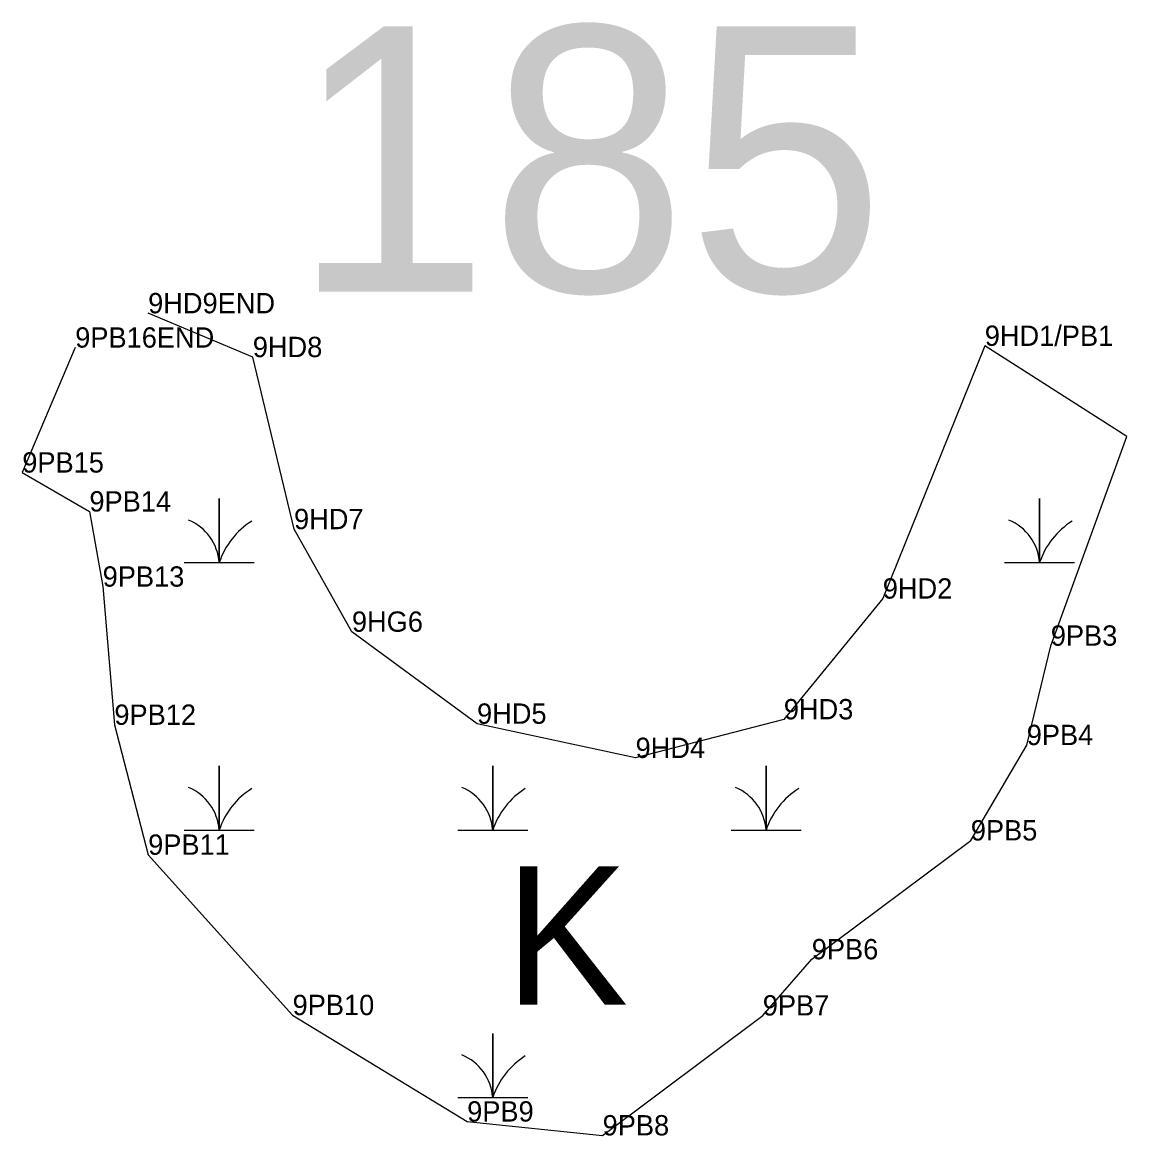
# Model space of a CAD drawing. Extents: x 2072529 to 2268796, y 436423 to 470406.
# Drawn here: x 2214651 to 2214922.6, y 450641.4 to 450915.4 of the extents above; entities that cross this region are included whole.
import ezdxf

# ---------------------------------------------------------------- set-up
doc = ezdxf.new("R2010")
doc.units = 0
for name, color, linetype in [('Default', 7, 'Continuous'), ('Exist Environmental Wetland Boundary', 7, 'Continuous'), ('Exist Environmental Wetland Boundary Cogo Comment', 7, 'Continuous'), ('Exist Hydro Swamp or Marsh', 7, 'Continuous'), ('Old_Level_20', 7, 'Continuous')]:
    doc.layers.add(name, color=color, linetype=linetype)

msp = doc.modelspace()

# ---------------------------------------------------------------- linework, layer by layer
at = {"layer": 'Exist Environmental Wetland Boundary'}
msp.add_lwpolyline([(2214663.98, 450835.35), (2214650.96, 450804.61), (2214667.47, 450795.03), (2214670.73, 450776.54), (2214673.61, 450742.54), (2214681.92, 450710.57), (2214717.44, 450671.12), (2214760.37, 450644.93), (2214793.69, 450641.52), (2214833.07, 450671.03), (2214845.12, 450684.85), (2214884.23, 450714.09), (2214897.98, 450737.56), (2214903.9, 450762.01), (2214922.57, 450813.5), (2214887.66, 450835.78), (2214862.58, 450773.6), (2214838.24, 450743.89), (2214801.78, 450734.39), (2214762.8, 450742.81), (2214732.03, 450765.44), (2214717.79, 450790.68), (2214707.65, 450833.02), (2214681.91, 450843.8)], dxfattribs=at)
at = {"layer": 'Exist Hydro Swamp or Marsh'}
for points in [[(2214690.8, 450782.46), (2214699.4, 450782.46), (2214699.4, 450798.24), (2214699.4, 450782.46), (2214708, 450782.46)], [(2214892.55, 450782.46), (2214901.15, 450782.46), (2214901.15, 450798.24), (2214901.15, 450782.46), (2214909.75, 450782.46)], [(2214690.8, 450716.66), (2214699.4, 450716.66), (2214699.4, 450732.44), (2214699.4, 450716.66), (2214708, 450716.66)], [(2214758.05, 450716.66), (2214766.65, 450716.66), (2214766.65, 450732.44), (2214766.65, 450716.66), (2214775.25, 450716.66)], [(2214825.3, 450716.66), (2214833.9, 450716.66), (2214833.9, 450732.44), (2214833.9, 450716.66), (2214842.5, 450716.66)], [(2214758.05, 450650.86), (2214766.65, 450650.86), (2214766.65, 450666.64), (2214766.65, 450650.86), (2214775.25, 450650.86)]]:
    msp.add_lwpolyline(points, dxfattribs=at)
for centre, radius, start, end in [((2214687.13, 450781.57), 12.3, 4.1403, 67.535), ((2214717.64, 450776.4), 19.22, 122.1274, 161.6222), ((2214888.88, 450781.57), 12.3, 4.1403, 67.535), ((2214919.39, 450776.4), 19.22, 122.1274, 161.6222), ((2214687.13, 450715.77), 12.3, 4.1403, 67.535), ((2214717.64, 450710.6), 19.22, 122.1274, 161.6222), ((2214754.38, 450715.77), 12.3, 4.1403, 67.535), ((2214784.89, 450710.6), 19.22, 122.1274, 161.6222), ((2214821.63, 450715.77), 12.3, 4.1403, 67.535), ((2214852.14, 450710.6), 19.22, 122.1274, 161.6222), ((2214754.38, 450649.97), 12.3, 4.1403, 67.535), ((2214784.89, 450644.8), 19.22, 122.1274, 161.6222)]:
    msp.add_arc(centre, radius, start, end, dxfattribs=at)
at = {"layer": 'Old_Level_20'}
for p, q in [((2214681.91, 450843.8), (2214681.91, 450843.8)), ((2214663.98, 450835.35), (2214663.98, 450835.35)), ((2214887.66, 450835.78), (2214887.66, 450835.78)), ((2214707.65, 450833.02), (2214707.65, 450833.02)), ((2214922.57, 450813.5), (2214922.57, 450813.5)), ((2214650.96, 450804.61), (2214650.96, 450804.61)), ((2214667.47, 450795.03), (2214667.47, 450795.03)), ((2214717.79, 450790.68), (2214717.79, 450790.68)), ((2214670.73, 450776.54), (2214670.73, 450776.54)), ((2214862.58, 450773.6), (2214862.58, 450773.6)), ((2214732.03, 450765.44), (2214732.03, 450765.44)), ((2214903.9, 450762.01), (2214903.9, 450762.01)), ((2214762.8, 450742.81), (2214762.8, 450742.81)), ((2214838.24, 450743.89), (2214838.24, 450743.89)), ((2214673.61, 450742.54), (2214673.61, 450742.54)), ((2214897.98, 450737.56), (2214897.98, 450737.56)), ((2214801.78, 450734.39), (2214801.78, 450734.39)), ((2214884.23, 450714.09), (2214884.23, 450714.09)), ((2214681.92, 450710.57), (2214681.92, 450710.57)), ((2214845.12, 450684.85), (2214845.12, 450684.85)), ((2214717.44, 450671.12), (2214717.44, 450671.12)), ((2214833.07, 450671.03), (2214833.07, 450671.03)), ((2214760.37, 450644.93), (2214760.37, 450644.93)), ((2214793.69, 450641.52), (2214793.69, 450641.52))]:
    msp.add_line(p, q, dxfattribs=at)

# ---------------------------------------------------------------- texts
at = {"layer": 'Default'}
msp.add_text('185', height=65.34, dxfattribs=at).set_placement((2214717.3, 450849.09))
at = {"layer": 'Exist Environmental Wetland Boundary Cogo Comment'}
for s, p in [('9HD9END', (2214681.91, 450843.8)), ('9PB16END', (2214663.98, 450835.35)), ('9HD1/PB1', (2214887.66, 450835.78)), ('9HD8', (2214707.65, 450833.02)), ('9PB15', (2214650.96, 450804.61)), ('9PB14', (2214667.47, 450795.03)), ('9HD7', (2214717.79, 450790.68)), ('9PB13', (2214670.73, 450776.54)), ('9HD2', (2214862.58, 450773.6)), ('9HG6', (2214732.03, 450765.44)), ('9PB3', (2214903.9, 450762.01)), ('9HD3', (2214838.24, 450743.89)), ('9PB12', (2214673.61, 450742.54)), ('9HD5', (2214762.8, 450742.81)), ('9PB4', (2214897.98, 450737.56)), ('9HD4', (2214801.78, 450734.39)), ('9PB5', (2214884.23, 450714.09)), ('9PB11', (2214681.92, 450710.57)), ('9PB6', (2214845.12, 450684.85)), ('9PB10', (2214717.44, 450671.12)), ('9PB7', (2214833.07, 450671.03)), ('9PB9', (2214760.37, 450644.93)), ('9PB8', (2214793.69, 450641.52))]:
    msp.add_text(s, height=5, dxfattribs=at).set_placement(p)
at = {"layer": 'Exist Hydro Swamp or Marsh'}
msp.add_text('K', height=34, dxfattribs=at).set_placement((2214769.65, 450673.69))

doc.saveas('drawing.dxf')
